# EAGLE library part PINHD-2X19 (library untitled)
PIN HEADER
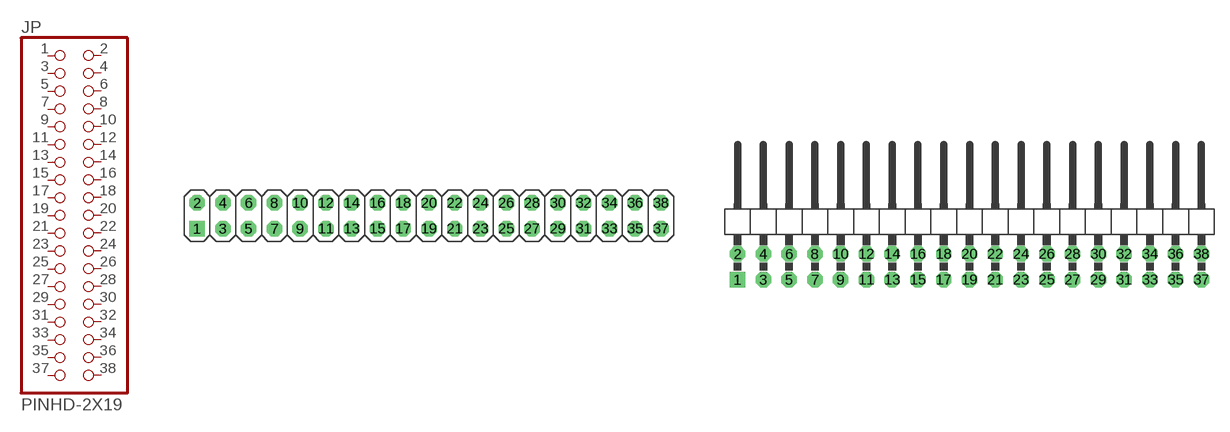
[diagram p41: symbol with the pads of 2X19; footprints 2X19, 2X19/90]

Designator prefix JP

## PINHD-2X19_2.54  [2X19]
1  1  pas
2  2  pas
3  3  pas
4  4  pas
5  5  pas
6  6  pas
7  7  pas
8  8  pas
9  9  pas
10  10  pas
11  11  pas
12  12  pas
13  13  pas
14  14  pas
15  15  pas
16  16  pas
17  17  pas
18  18  pas
19  19  pas
20  20  pas
21  21  pas
22  22  pas
23  23  pas
24  24  pas
25  25  pas
26  26  pas
27  27  pas
28  28  pas
29  29  pas
30  30  pas
31  31  pas
32  32  pas
33  33  pas
34  34  pas
35  35  pas
36  36  pas
37  37  pas
38  38  pas

## PINHD-2X19_2.54-90°  [2X19/90]
Pads as for 2X19

## PINHD-2X19_2.00  [2X19M]
Pads as for 2X19

## PINHD-2X19_2.54-SMD  [2X19SMD]
Pads as for 2X19

## PINHD-2X19_2.54-SMD-90°  [2X19SMD/90]
Pads as for 2X19

## Footprint 2X19 (pad centres in mm)
PIN HEADER - 2.54
drill 1.016 square: 1 -22.86,-1.27
drill 1.016 octagon: 2 -22.86,1.27; 3 -20.32,-1.27; 4 -20.32,1.27; 5 -17.78,-1.27; 6 -17.78,1.27; 7 -15.24,-1.27; 8 -15.24,1.27; 9 -12.7,-1.27; 10 -12.7,1.27; 11 -10.16,-1.27; 12 -10.16,1.27; 13 -7.62,-1.27; 14 -7.62,1.27; 15 -5.08,-1.27; 16 -5.08,1.27; 17 -2.54,-1.27; 18 -2.54,1.27; 19 0,-1.27; 20 0,1.27; 21 2.54,-1.27; 22 2.54,1.27; 23 5.08,-1.27; 24 5.08,1.27; 25 7.62,-1.27; 26 7.62,1.27; 27 10.16,-1.27; 28 10.16,1.27; 29 12.7,-1.27; 30 12.7,1.27; 31 15.24,-1.27; 32 15.24,1.27; 33 17.78,-1.27; 34 17.78,1.27; 35 20.32,-1.27; 36 20.32,1.27; 37 22.86,-1.27; 38 22.86,1.27

## Footprint 2X19/90 (pad centres in mm)
PIN HEADER - 2.54 90°
drill 1.016 square: 1 -22.86,-6.35
drill 1.016 octagon: 2 -22.86,-3.81; 3 -20.32,-6.35; 4 -20.32,-3.81; 5 -17.78,-6.35; 6 -17.78,-3.81; 7 -15.24,-6.35; 8 -15.24,-3.81; 9 -12.7,-6.35; 10 -12.7,-3.81; 11 -10.16,-6.35; 12 -10.16,-3.81; 13 -7.62,-6.35; 14 -7.62,-3.81; 15 -5.08,-6.35; 16 -5.08,-3.81; 17 -2.54,-6.35; 18 -2.54,-3.81; 19 0,-6.35; 20 0,-3.81; 21 2.54,-6.35; 22 2.54,-3.81; 23 5.08,-6.35; 24 5.08,-3.81; 25 7.62,-6.35; 26 7.62,-3.81; 27 10.16,-6.35; 28 10.16,-3.81; 29 12.7,-6.35; 30 12.7,-3.81; 31 15.24,-6.35; 32 15.24,-3.81; 33 17.78,-6.35; 34 17.78,-3.81; 35 20.32,-6.35; 36 20.32,-3.81; 37 22.86,-6.35; 38 22.86,-3.81

## Footprint 2X19M (pad centres in mm)
PIN HEADER - 2
drill 0.914 square: 1 -18,-1
drill 0.914 round: 2 -18,1; 3 -16,-1; 4 -16,1; 5 -14,-1; 6 -14,1; 7 -12,-1; 8 -12,1; 9 -10,-1; 10 -10,1; 11 -8,-1; 12 -8,1; 13 -6,-1; 14 -6,1; 15 -4,-1; 16 -4,1; 17 -2,-1; 18 -2,1; 19 0,-1; 20 0,1; 21 2,-1; 22 2,1; 23 4,-1; 24 4,1; 25 6,-1; 26 6,1; 27 8,-1; 28 8,1; 29 10,-1; 30 10,1; 31 12,-1; 32 12,1; 33 14,-1; 34 14,1; 35 16,-1; 36 16,1; 37 18,-1; 38 18,1

## Footprint 2X19SMD (pad centres in mm)
PIN HEADER - 2.54 SMD
smd 1.016 x 3.302: 1 -1.27,-3.81; 2 -1.27,1.27; 3 1.27,-3.81; 4 1.27,1.27; 5 3.81,-3.81; 6 3.81,1.27; 7 6.35,-3.81; 8 6.35,1.27; 9 8.89,-3.81; 10 8.89,1.27; 11 11.43,-3.81; 12 11.43,1.27; 13 13.97,-3.81; 14 13.97,1.27; 15 16.51,-3.81; 16 16.51,1.27; 17 19.05,-3.81; 18 19.05,1.27; 19 21.59,-3.81; 20 21.59,1.27; 21 24.13,-3.81; 22 24.13,1.27; 23 26.67,-3.81; 24 26.67,1.27; 25 29.21,-3.81; 26 29.21,1.27; 27 31.75,-3.81; 28 31.75,1.27; 29 34.29,-3.81; 30 34.29,1.27; 31 36.83,-3.81; 32 36.83,1.27; 33 39.37,-3.81; 34 39.37,1.27; 35 41.91,-3.81; 36 41.91,1.27; 37 44.45,-3.81; 38 44.45,1.27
